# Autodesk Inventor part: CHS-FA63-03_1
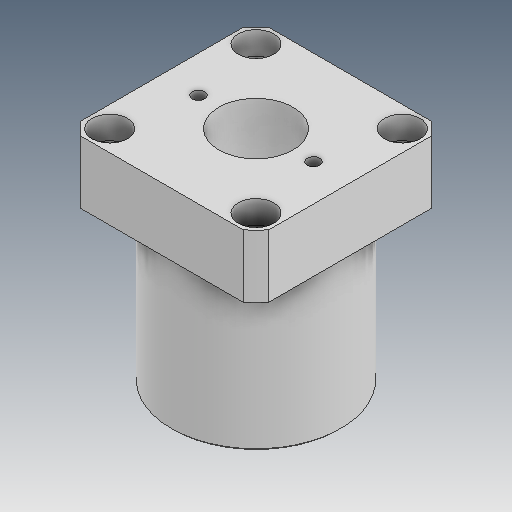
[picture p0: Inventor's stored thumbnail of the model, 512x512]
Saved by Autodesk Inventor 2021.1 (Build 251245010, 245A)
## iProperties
Created: 2019-05
Part Number: CHS-FA63-03_1
Material: Ogólny
Document SubType Name: Modeling
Designer: user
Density: 1 g/cm^3
Appearance: Domyślna
Author: user
Revision Number: ÈÎºÎ
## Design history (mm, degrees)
feature "ÊäÈë1"
node "Bryła1"
